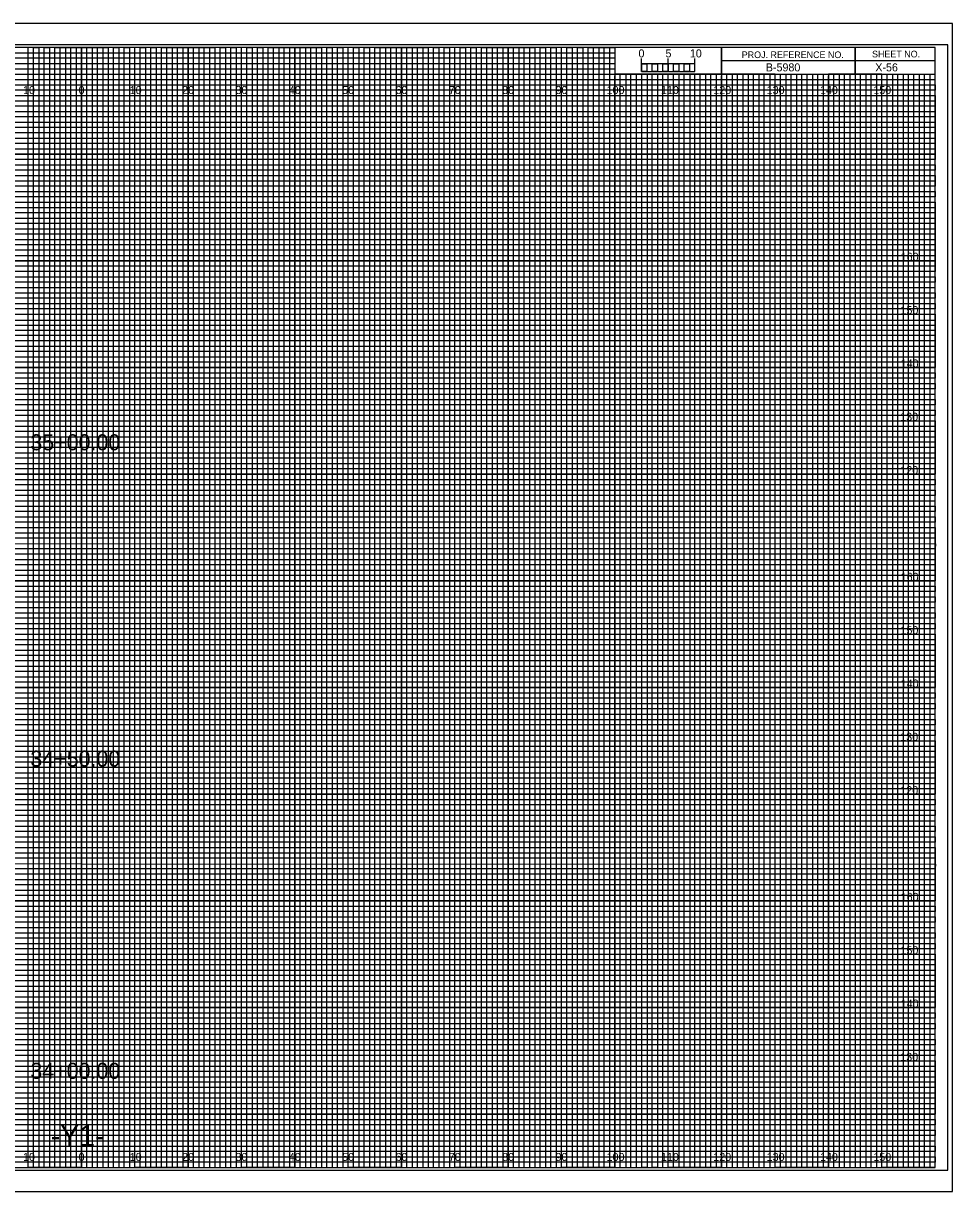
# Model space of a CAD drawing. Extents: x -13 to 323, y -5 to 4834.
# Drawn here: x 149.1 to 323.3, y 2195.5 to 2414.5 of the extents above; entities that cross this region are included whole.
import ezdxf

# ---------------------------------------------------------------- set-up
doc = ezdxf.new("R2010")
doc.units = 0
for name, color, linetype in [('Exist CMT Pavement', 7, 'Continuous'), ('Exist Cross Section Cell', 7, 'Continuous'), ('Exist XS Center Line Elevation Label', 7, 'Continuous'), ('Exist XS Ground Line', 7, 'Continuous'), ('Prop CMT Pvmt Course 1', 7, 'Continuous'), ('Prop CMT Pvmt Course 1 Wedge', 7, 'Continuous'), ('Prop CMT Pvmt Course 2', 7, 'Continuous'), ('Prop CMT Pvmt Course 2 Wedge', 7, 'Continuous'), ('Prop CMT Pvmt Course 3', 7, 'Continuous'), ('Prop CMT Pvmt Course 3 Wedge', 7, 'Continuous'), ('Prop CMT Pvmt Surface', 7, 'Continuous'), ('Prop CMT Pvmt Surface Shoulder', 7, 'Continuous'), ('Prop CMT Shld Paved Course 1', 7, 'Continuous'), ('Prop CMT Shld Paved Course 2', 7, 'Continuous'), ('Prop CMT Shld Paved Course 3', 7, 'Continuous'), ('Prop CMT Slope Grass', 7, 'Continuous'), ('Prop CMT Subgrade Earthwork', 7, 'Continuous')]:
    doc.layers.add(name, color=color, linetype=linetype)

msp = doc.modelspace()

# ---------------------------------------------------------------- linework, layer by layer
at = {"layer": 'Exist XS Center Line Elevation Label'}
for points in [[(145, 2200), (155, 2200), (155, 2410), (165, 2410), (165, 2200), (175, 2200), (175, 2410), (185, 2410), (185, 2200), (195, 2200), (195, 2410), (205, 2410), (205, 2200), (215, 2200), (215, 2410), (225, 2410), (225, 2200), (235, 2200), (235, 2410), (245, 2410), (245, 2200), (255, 2200), (255, 2410), (259.93, 2410), (260, 2410), (260, 2405), (264.99, 2405), (264.99, 2200), (275, 2200), (275, 2405), (285, 2405), (285, 2200), (295, 2200), (295, 2405), (305, 2405), (305, 2200), (315, 2200), (315, 2405)], [(0, 2405), (275, 2405)], [(0, 2385), (320, 2385), (320, 2395), (0, 2395)], [(0, 2365), (320, 2365), (320, 2375), (0, 2375)], [(0, 2345), (320, 2345), (320, 2355), (0, 2355)], [(0, 2325), (320, 2325), (320, 2335), (0, 2335)], [(0, 2305), (320, 2305), (320, 2315), (0, 2315)], [(0, 2285), (320, 2285), (320, 2295), (0, 2295)], [(0, 2265), (320, 2265), (320, 2275), (0, 2275)], [(0, 2245), (320, 2245), (320, 2255), (0, 2255)], [(0, 2225), (320, 2225), (320, 2235), (0, 2235)], [(0, 2205), (320, 2205), (320, 2215), (0, 2215)]]:
    msp.add_lwpolyline(points, dxfattribs=at)
at = {"layer": 'Exist XS Ground Line'}
for p, q in [((150, 2410), (140, 2410)), ((150, 2200), (150, 2410)), ((170, 2410), (160, 2410)), ((160, 2410), (160, 2200)), ((170, 2200), (170, 2410)), ((190, 2410), (180, 2410)), ((180, 2410), (180, 2200)), ((190, 2200), (190, 2410)), ((210, 2410), (200, 2410)), ((200, 2410), (200, 2200)), ((210, 2200), (210, 2410)), ((230, 2410), (220, 2410)), ((220, 2410), (220, 2200)), ((230, 2200), (230, 2410)), ((250, 2410), (240, 2410)), ((240, 2410), (240, 2200)), ((250, 2200), (250, 2410)), ((260, 2410), (260, 2200)), ((270, 2200), (270, 2405)), ((290, 2405), (280, 2405)), ((280, 2405), (280, 2200)), ((290, 2200), (290, 2405)), ((310, 2405), (300, 2405)), ((300, 2405), (300, 2200)), ((310, 2200), (310, 2405)), ((160, 2200), (150, 2200)), ((180, 2200), (170, 2200)), ((200, 2200), (190, 2200)), ((220, 2200), (210, 2200)), ((240, 2200), (230, 2200)), ((260, 2200), (250, 2200)), ((280, 2200), (270, 2200)), ((300, 2200), (290, 2200)), ((320, 2200), (310, 2200)), ((320, 2200), (320, 2200))]:
    msp.add_line(p, q, dxfattribs=at)
for points in [[(0, 2400), (320, 2400), (320, 2390), (0, 2390)], [(0, 2380), (320, 2380), (320, 2370), (0, 2370)], [(0, 2360), (320, 2360), (320, 2350), (0, 2350)], [(0, 2340), (320, 2340), (320, 2330), (0, 2330)], [(0, 2320), (320, 2320), (320, 2310), (0, 2310)], [(0, 2300), (320, 2300), (320, 2290), (0, 2290)], [(0, 2280), (320, 2280), (320, 2270), (0, 2270)], [(0, 2260), (320, 2260), (320, 2250), (0, 2250)], [(0, 2240), (320, 2240), (320, 2230), (0, 2230)], [(0, 2220), (320, 2220), (320, 2210), (0, 2210)]]:
    msp.add_lwpolyline(points, dxfattribs=at)
at = {"layer": 'Prop CMT Pvmt Course 1'}
for p, q in [((267, 2405), (266.01, 2405)), ((266.01, 2405), (266.01, 2200)), ((267, 2200), (267, 2405)), ((269, 2405), (268, 2405)), ((268, 2405), (268, 2200)), ((269, 2200), (269, 2405)), ((266.01, 2200), (265, 2200)), ((268, 2200), (267, 2200))]:
    msp.add_line(p, q, dxfattribs=at)
for points in [[(150, 2200), (151, 2200), (151, 2410), (152, 2410), (152, 2200)], [(152, 2200), (153, 2200), (153, 2410), (154, 2410), (154, 2200)], [(155, 2200), (156, 2200), (156, 2410), (157, 2410), (157, 2200)], [(157, 2200), (158, 2200), (158, 2410), (159, 2410), (159, 2200)], [(160, 2200), (161, 2200), (161, 2410), (162, 2410), (162, 2200)], [(162, 2200), (163, 2200), (163, 2410), (164, 2410), (164, 2200)], [(165, 2200), (166, 2200), (166, 2410), (167, 2410), (167, 2200)], [(167, 2200), (168, 2200), (168, 2410), (169, 2410), (169, 2200)], [(170, 2200), (171, 2200), (171, 2410), (172, 2410), (172, 2200)], [(172, 2200), (173, 2200), (173, 2410), (174, 2410), (174, 2200)], [(175, 2200), (176, 2200), (176, 2410), (177, 2410), (177, 2200)], [(177, 2200), (178, 2200), (178, 2410), (179, 2410), (179, 2200)], [(180, 2200), (181, 2200), (181, 2410), (182, 2410), (182, 2200)], [(182, 2200), (183, 2200), (183, 2410), (184, 2410), (184, 2200)], [(185, 2200), (186, 2200), (186, 2410), (187, 2410), (187, 2200)], [(187, 2200), (188, 2200), (188, 2410), (189, 2410), (189, 2200)], [(190, 2200), (191, 2200), (191, 2410), (192, 2410), (192, 2200)], [(192, 2200), (193, 2200), (193, 2410), (194, 2410), (194, 2200)], [(195, 2200), (196, 2200), (196, 2410), (197, 2410), (197, 2200)], [(197, 2200), (198, 2200), (198, 2410), (199, 2410), (199, 2200)], [(200, 2200), (201, 2200), (201, 2410), (202, 2410), (202, 2200)], [(202, 2200), (203, 2200), (203, 2410), (204, 2410), (204, 2200)], [(205, 2200), (206, 2200), (206, 2410), (207, 2410), (207, 2200)], [(207, 2200), (208, 2200), (208, 2410), (209, 2410), (209, 2200)], [(210, 2200), (211, 2200), (211, 2410), (212, 2410), (212, 2200)], [(212, 2200), (213, 2200), (213, 2410), (214, 2410), (214, 2200)], [(215, 2200), (216, 2200), (216, 2410), (217, 2410), (217, 2200)], [(217, 2200), (218, 2200), (218, 2410), (219, 2410), (219, 2200)], [(220, 2200), (221, 2200), (221, 2410), (222, 2410), (222, 2200)], [(222, 2200), (223, 2200), (223, 2410), (224, 2410), (224, 2200)], [(225, 2200), (226, 2200), (226, 2410), (227, 2410), (227, 2200)], [(227, 2200), (228, 2200), (228, 2410), (229, 2410), (229, 2200)], [(230, 2200), (231, 2200), (231, 2410), (232, 2410), (232, 2200)], [(232, 2200), (233, 2200), (233, 2410), (234, 2410), (234, 2200)], [(235, 2200), (236, 2200), (236, 2410), (237, 2410), (237, 2200)], [(237, 2200), (238, 2200), (238, 2410), (239, 2410), (239, 2200)], [(240, 2200), (241, 2200), (241, 2410), (242, 2410), (242, 2200)], [(242, 2200), (243, 2200), (243, 2410), (244, 2410), (244, 2200)], [(245, 2200), (246, 2200), (246, 2410), (247, 2410), (247, 2200)], [(247, 2200), (248, 2200), (248, 2410), (249, 2410), (249, 2200)], [(250, 2200), (251, 2200), (251, 2410), (252, 2410), (252, 2200)], [(252, 2200), (253, 2200), (253, 2410), (254, 2410), (254, 2200)], [(255, 2200), (256, 2200), (256, 2410), (257, 2410), (257, 2200)], [(257, 2200), (258, 2200), (258, 2410), (259, 2410), (259, 2200)], [(260, 2200), (261, 2200), (261, 2405), (262.02, 2405), (262.02, 2200)], [(262, 2200), (263, 2200), (263, 2405), (263.99, 2405), (263.99, 2200)], [(270, 2200), (270.98, 2200), (270.98, 2405), (272, 2405), (272, 2200)], [(272, 2200), (273, 2200), (273, 2405), (274.05, 2405), (274.05, 2200)], [(275, 2200), (276, 2200), (276, 2405), (277, 2405), (277, 2200)], [(277, 2200), (278, 2200), (278, 2405), (279, 2405), (279, 2200)], [(280, 2200), (281, 2200), (281, 2405), (282, 2405), (282, 2200)], [(282, 2200), (283, 2200), (283, 2405), (284, 2405), (284, 2200)], [(285, 2200), (286, 2200), (286, 2405), (287, 2405), (287, 2200)], [(287, 2200), (288, 2200), (288, 2405), (289, 2405), (289, 2200)], [(290, 2200), (291, 2200), (291, 2405), (292, 2405), (292, 2200)], [(292, 2200), (293, 2200), (293, 2405), (294, 2405), (294, 2200)], [(295, 2200), (296, 2200), (296, 2405), (297, 2405), (297, 2200)], [(297, 2200), (298, 2200), (298, 2405), (299, 2405), (299, 2200)], [(300, 2200), (301, 2200), (301, 2405), (302, 2405), (302, 2200)], [(302, 2200), (303, 2200), (303, 2405), (304, 2405), (304, 2200)], [(305, 2200), (306, 2200), (306, 2405), (307, 2405), (307, 2200)], [(307, 2200), (308, 2200), (308, 2405), (309, 2405), (309, 2200)], [(310, 2200), (311, 2200), (311, 2405), (312, 2405), (312, 2200)], [(312, 2200), (313, 2200), (313, 2405), (314, 2405), (314, 2200)], [(315, 2200), (316, 2200), (316, 2405), (317, 2405), (317, 2200)], [(317, 2200), (318, 2200), (318, 2405), (319, 2405), (319, 2200)]]:
    msp.add_lwpolyline(points, dxfattribs=at)
at = {"layer": 'Prop CMT Pvmt Course 2'}
for p, q in [((323.3, 2414.5), (-13.4, 2414.5)), ((-13.4, 2195.5), (323.3, 2195.5))]:
    msp.add_line(p, q, dxfattribs=at)
at = {"layer": 'Prop CMT Pvmt Surface Shoulder'}
for p, q in [((305, 2410), (305, 2405)), ((305, 2405), (305, 2410)), ((280, 2407.5), (280, 2405)), ((320, 2407.49), (280, 2407.49)), ((280, 2405), (320, 2405))]:
    msp.add_line(p, q, dxfattribs=at)
for points in [[(320, 2410), (0, 2410), (0, 2200), (320, 2200)], [(280, 2410), (260, 2410), (260, 2405.03), (280, 2405.03)], [(320, 2410), (280, 2410), (280, 2405), (320, 2405)]]:
    msp.add_lwpolyline(points, close=True, dxfattribs=at)
at = {"layer": 'Prop CMT Shld Paved Course 1'}
msp.add_lwpolyline([(-13.4, 2195.5), (323.3, 2195.5), (323.3, 2414.5), (-13.4, 2414.5)], close=True, dxfattribs=at)
at = {"layer": 'Prop CMT Shld Paved Course 2'}
msp.add_lwpolyline([(-10.8, 2199.5), (322.4, 2199.5), (322.4, 2410.5), (-10.8, 2410.5)], close=True, dxfattribs=at)
at = {"layer": 'Prop CMT Shld Paved Course 3'}
for p, q in [((150, 2200), (150, 2410)), ((160, 2200), (160, 2410)), ((170, 2200), (170, 2410)), ((180, 2200), (180, 2410)), ((190, 2200), (190, 2410)), ((200, 2200), (200, 2410)), ((210, 2200), (210, 2410)), ((220, 2200), (220, 2410)), ((230, 2200), (230, 2410)), ((240, 2200), (240, 2410)), ((250, 2200), (250, 2410)), ((260, 2200), (260, 2404.69)), ((270, 2200), (270, 2404.69)), ((280, 2200), (280, 2404.69)), ((290, 2200), (290, 2404.69)), ((300, 2200), (300, 2404.69)), ((310, 2200), (310, 2404.69)), ((0, 2400), (320, 2400)), ((0, 2390), (320, 2390)), ((0, 2380), (320, 2380)), ((0, 2370), (320, 2370)), ((0, 2360), (320, 2360)), ((0, 2350), (320, 2350)), ((0, 2340), (320, 2340)), ((0, 2330), (320, 2330)), ((0, 2320), (320, 2320)), ((0, 2310), (320, 2310)), ((0, 2300), (320, 2300)), ((0, 2290), (320, 2290)), ((0, 2280), (320, 2280)), ((0, 2270), (320, 2270)), ((0, 2260), (320, 2260)), ((0, 2250), (320, 2250)), ((0, 2240), (320, 2240)), ((0, 2230), (320, 2230)), ((0, 2220), (320, 2220)), ((0, 2210), (320, 2210))]:
    msp.add_line(p, q, dxfattribs=at)
at = {"layer": 'Prop CMT Slope Grass'}
for p, q in [((0, 2409), (260, 2409)), ((260, 2409), (260, 2407.98)), ((260, 2407.98), (0, 2407.98)), ((0, 2407), (260, 2407)), ((260, 2407), (260, 2405.89)), ((260, 2405.89), (0, 2405.89)), ((0, 2404), (320, 2404))]:
    msp.add_line(p, q, dxfattribs=at)
for points in [[(0, 2403), (270, 2403), (320, 2403), (320, 2402), (0, 2402)], [(0, 2401), (320, 2401), (320, 2399), (0, 2399)], [(0, 2398), (320, 2398), (320, 2397), (0, 2396.98)], [(0, 2396), (320, 2396), (320, 2394), (0, 2394)], [(0, 2393), (320, 2393), (320, 2392), (0, 2392)], [(0, 2391), (320, 2391), (320, 2389), (0, 2389)], [(0, 2388), (320, 2388), (320, 2387), (0, 2387)], [(0, 2386), (320, 2386), (320, 2384), (0, 2384)], [(0, 2383), (320, 2383), (320, 2382), (0, 2382)], [(0, 2381), (320, 2381), (320, 2379), (0, 2379)], [(0, 2378), (320, 2378), (320, 2377), (0, 2377)], [(0, 2376), (320, 2376), (320, 2373.95), (320, 2373), (320, 2372), (0, 2372)], [(0, 2374), (320, 2374), (320, 2373), (0, 2373)], [(0, 2371), (320, 2371), (320, 2369), (0, 2369.03)], [(0, 2369.03), (320, 2369), (320, 2368), (0, 2368)], [(0, 2367), (320, 2367), (320, 2366), (0, 2366)], [(0, 2364), (320, 2364), (320, 2363), (0, 2363)], [(0, 2362), (320, 2362), (320, 2361), (0, 2361)], [(-0.07, 2358.89), (320, 2358.89), (320, 2357.88), (-0.07, 2357.88)], [(0, 2357), (320, 2357), (320, 2356), (0, 2356)], [(0, 2354), (320, 2354), (320, 2353), (0, 2353)], [(0, 2352), (320, 2352), (320, 2351), (0, 2351)], [(0, 2349), (320, 2349), (320, 2348), (0, 2348)], [(0, 2347), (320, 2347), (320, 2346), (0, 2346)], [(0, 2344), (320, 2344), (320, 2343), (0, 2343)], [(0, 2342), (320, 2342), (320, 2341), (0, 2341)], [(0, 2339), (320, 2339), (319.99, 2337.98), (0, 2338)], [(0, 2337), (320, 2337), (320, 2336), (0, 2336)], [(0, 2334), (320, 2334), (320, 2333), (0, 2333)], [(0, 2332), (320, 2332), (320, 2331), (0, 2331)], [(0, 2329), (320, 2329), (320, 2328), (0, 2328)], [(0, 2327), (320, 2327), (320, 2326), (0, 2326)], [(0, 2324), (320, 2324), (320, 2323), (0, 2323)], [(0, 2322), (320, 2322), (320, 2321), (0, 2321)], [(0, 2319), (320, 2319), (320, 2318), (0, 2318)], [(0, 2316.99), (320.07, 2316.91), (320, 2316), (0, 2316)], [(0, 2314), (320, 2314), (320, 2313), (0, 2313)], [(0, 2312), (320, 2312), (320, 2311), (0, 2311)], [(0, 2309), (320, 2309), (320, 2308), (0, 2308)], [(0, 2307), (320, 2307), (320, 2306), (0, 2306)], [(0, 2304), (320, 2304), (320, 2303), (0, 2303)], [(0, 2302), (320, 2302), (320, 2301), (0, 2301)], [(0, 2299), (320, 2299), (320, 2298), (0, 2298)], [(0, 2297), (320, 2297), (320, 2296), (0, 2296)], [(0, 2294), (320, 2294), (320, 2293), (0, 2293)], [(0, 2292), (320, 2292), (320, 2291), (0, 2291)], [(0, 2289), (320, 2289), (320, 2288), (0, 2288)], [(0, 2287), (320, 2287), (320, 2286), (0, 2286)], [(0, 2284), (320, 2284), (320, 2283), (0, 2283)], [(0, 2282), (320, 2282), (320, 2281), (0, 2281)], [(0, 2279), (320, 2279), (319.99, 2277.98), (0, 2278)], [(0, 2277), (320, 2277), (320, 2276), (0, 2276)], [(0, 2274), (320, 2274), (320, 2273), (0, 2273)], [(0, 2272), (320, 2272), (320, 2271), (0, 2271)], [(0, 2269), (320, 2269), (320, 2268), (0, 2268)], [(0, 2267), (320, 2267), (320, 2266), (0, 2266)], [(0, 2264), (320, 2264), (320, 2263), (0, 2263)], [(0, 2262), (320, 2262), (320, 2261), (0, 2261)], [(0, 2259), (320, 2259), (320, 2258), (0, 2258)], [(0, 2256.99), (320.07, 2256.91), (320, 2256), (0, 2256)], [(0, 2254), (320, 2254), (320, 2253), (0, 2253)], [(0, 2252), (320, 2252), (320, 2251), (0, 2251)], [(0, 2249), (320, 2249), (320, 2248), (0, 2248)], [(0, 2247), (320, 2247), (320, 2246), (0, 2246)], [(0, 2244), (320, 2244), (320, 2243), (0, 2243)], [(0, 2242), (320, 2242), (320, 2241), (0, 2241)], [(0, 2239), (320, 2239), (320, 2238), (0, 2238)], [(0, 2237), (320, 2237), (320, 2236), (0, 2236)], [(0, 2234), (320, 2234), (320, 2233), (0, 2233)], [(0, 2232), (320, 2232), (320, 2231), (0, 2231)], [(0, 2229), (320, 2229), (320, 2228), (0, 2228)], [(0, 2227), (320, 2227), (320, 2226), (0, 2226)], [(0, 2224), (320, 2224), (320, 2223), (0, 2223)], [(0, 2222), (320, 2222), (320, 2221), (0, 2221)], [(0, 2219), (320, 2219), (320, 2218), (0, 2218)], [(0, 2217), (320, 2217), (320, 2216), (0, 2216)], [(0, 2214), (320, 2214), (320, 2213), (0, 2213)], [(0, 2212), (320, 2212), (320, 2211), (0, 2211)], [(0, 2209), (320, 2209), (320, 2208), (0, 2208)], [(0, 2207), (320, 2207), (320, 2206), (0, 2206)], [(0, 2204), (320, 2204), (320, 2203), (0, 2203)], [(0, 2202), (320, 2202), (320, 2201), (0, 2201)]]:
    msp.add_lwpolyline(points, dxfattribs=at)
at = {"layer": 'Prop CMT Subgrade Earthwork'}
for p, q in [((265, 2405.49), (265, 2407.9)), ((265, 2406.9), (265, 2407.9)), ((270, 2405.49), (270, 2407.9)), ((275, 2405.49), (275, 2407.9)), ((275, 2406.9), (275, 2407.9))]:
    msp.add_line(p, q, dxfattribs=at)
for points in [[(275, 2406.9), (265, 2406.9), (265, 2405.49), (275, 2405.49)], [(265, 2406.9), (266, 2406.9), (266, 2405.49), (265, 2405.49)], [(267, 2406.9), (268, 2406.9), (268, 2405.49), (267, 2405.49)], [(269, 2406.9), (270, 2406.9), (270, 2405.49), (269, 2405.49)], [(271, 2406.9), (272, 2406.9), (272, 2405.49), (271, 2405.49)], [(273, 2406.9), (274, 2406.9), (274, 2405.49), (273, 2405.49)]]:
    msp.add_lwpolyline(points, close=True, dxfattribs=at)

# ---------------------------------------------------------------- texts
at = {"layer": 'Exist CMT Pavement'}
msp.add_text('-Y1-', height=4, dxfattribs=at).set_placement((154.21, 2204))
at = {"layer": 'Exist Cross Section Cell'}
for s, p in [('10', (149.04, 2401.25)), ('0', (159.45, 2401.25)), ('0', (159.45, 2401.25)), ('10', (169.04, 2401.25)), ('20', (178.86, 2401.25)), ('30', (188.86, 2401.25)), ('40', (198.86, 2401.25)), ('50', (208.86, 2401.25)), ('60', (218.86, 2401.25)), ('70', (228.86, 2401.25)), ('80', (238.86, 2401.25)), ('90', (248.86, 2401.25)), ('100', (258.44, 2401.25)), ('110', (268.62, 2401.25)), ('120', (278.44, 2401.25)), ('130', (288.44, 2401.25)), ('140', (298.44, 2401.25)), ('150', (308.44, 2401.25)), ('10', (149.04, 2201.25)), ('0', (159.45, 2201.25)), ('0', (159.45, 2201.25)), ('10', (169.04, 2201.25)), ('20', (178.86, 2201.25)), ('30', (188.86, 2201.25)), ('40', (198.86, 2201.25)), ('50', (208.86, 2201.25)), ('60', (218.86, 2201.25)), ('70', (228.86, 2201.25)), ('80', (238.86, 2201.25)), ('90', (248.86, 2201.25)), ('100', (258.44, 2201.25)), ('110', (268.62, 2201.25)), ('120', (278.44, 2201.25)), ('130', (288.44, 2201.25)), ('140', (298.44, 2201.25)), ('150', (308.44, 2201.25))]:
    msp.add_text(s, height=1.5, dxfattribs=at).set_placement(p)
at = {"layer": 'Prop CMT Pvmt Course 1 Wedge'}
for s, p in [('35+00.00', (150.41, 2334.47)), ('34+50.00', (150.41, 2275.17)), ('34+00.00', (150.41, 2216.65))]:
    msp.add_text(s, height=3, dxfattribs=at).set_placement(p)
at = {"layer": 'Prop CMT Pvmt Course 2 Wedge'}
msp.add_text('X-56', height=1.5, dxfattribs=at).set_placement((308.8, 2405.5))
at = {"layer": 'Prop CMT Pvmt Course 3'}
for s, p in [('160', (313.57, 2370)), ('150', (313.52, 2360)), ('140', (313.57, 2350)), ('130', (313.49, 2340)), ('120', (313.5, 2330)), ('160', (313.57, 2310)), ('150', (313.52, 2300)), ('140', (313.57, 2290)), ('130', (313.49, 2280)), ('120', (313.5, 2270)), ('160', (313.57, 2250)), ('150', (313.52, 2240)), ('140', (313.57, 2230)), ('130', (313.49, 2220))]:
    msp.add_text(s, height=1.5, dxfattribs=at).set_placement(p)
at = {"layer": 'Prop CMT Pvmt Course 3 Wedge'}
msp.add_text('B-5980', height=1.5, dxfattribs=at).set_placement((288.28, 2405.5))
at = {"layer": 'Prop CMT Pvmt Surface'}
for s, p in [('5', (269.47, 2408.12)), ('10', (274.04, 2408.12))]:
    msp.add_text(s, height=1.5, dxfattribs=at).set_placement(p)
at = {"layer": 'Prop CMT Pvmt Surface Shoulder'}
for s, p in [('PROJ. REFERENCE NO.', (283.77, 2407.99)), ('SHEET NO.', (308.19, 2408.12))]:
    msp.add_text(s, height=1.25, dxfattribs=at).set_placement(p)
at = {"layer": 'Prop CMT Subgrade Earthwork'}
msp.add_text('0', height=1.5, dxfattribs=at).set_placement((264.41, 2408.12))

doc.saveas('drawing.dxf')
